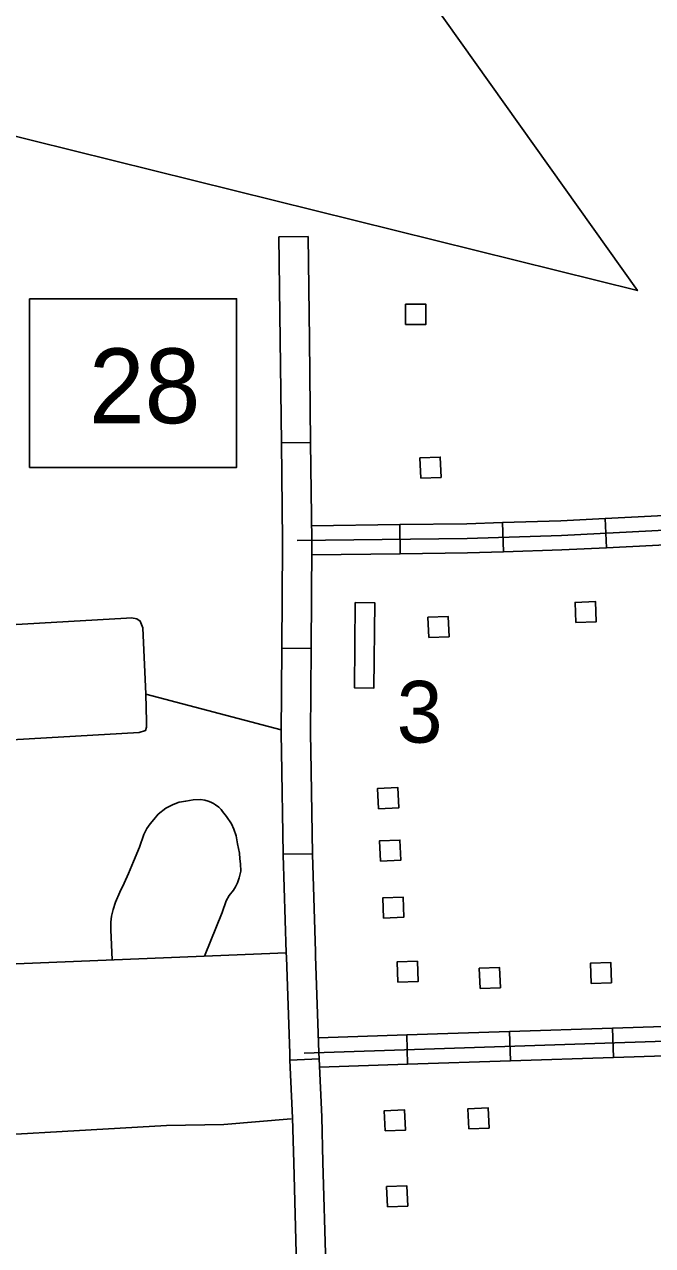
# Model space of a CAD drawing. Extents: x 1671357 to 13005564, y 567358 to 14261451.
# Drawn here: x 12758301.586 to 12758302.662, y 14259942.041 to 14259944.134 of the extents above; entities that cross this region are included whole.
import ezdxf

# ---------------------------------------------------------------- set-up
doc = ezdxf.new("R2010")
doc.units = 0
for name, color, linetype in [('31', 7, 'Continuous'), ('32', 7, 'Continuous'), ('56', 7, 'Continuous'), ('Default', 7, 'Continuous')]:
    doc.layers.add(name, color=color, linetype=linetype)

msp = doc.modelspace()

# ---------------------------------------------------------------- linework, layer by layer
at = {"layer": '31'}
for p, q in [((12758302.0222, 14259943.7697), (12758302.0722, 14259943.7703)), ((12758302.0764, 14259943.4177), (12758302.0263, 14259943.4171)), ((12758302.0771, 14259943.0647), (12758302.027, 14259943.0651)), ((12758302.0295, 14259942.7119), (12758302.0795, 14259942.7128)), ((12758302.041, 14259942.3589), (12758302.091, 14259942.3611)), ((12758302.041, 14259942.3589), (12758302.041, 14259942.3589))]:
    msp.add_line(p, q, dxfattribs=at)
for points in [[(12758302.0242, 14259943.5934), (12758302.0222, 14259943.7697)], [(12758302.0722, 14259943.7703), (12758302.0743, 14259943.594)], [(12758302.0263, 14259943.4171), (12758302.0242, 14259943.5934)], [(12758302.0743, 14259943.594), (12758302.0764, 14259943.4177)], [(12758302.0263, 14259943.4171), (12758302.0283, 14259943.2493), (12758302.0282, 14259943.2413)], [(12758302.0764, 14259943.4177), (12758302.0783, 14259943.2495), (12758302.0783, 14259943.241)], [(12758302.0282, 14259943.2413), (12758302.027, 14259943.0651)], [(12758302.0783, 14259943.241), (12758302.0771, 14259943.0647)], [(12758301.4006, 14259943.0738), (12758301.4045, 14259943.0354), (12758301.4372, 14259943.0364), (12758301.4715, 14259943.0382), (12758301.4876, 14259943.0453), (12758301.507, 14259943.0599), (12758301.5378, 14259943.0907), (12758301.5467, 14259943.1004), (12758301.5625, 14259943.1048), (12758301.7611, 14259943.1166), (12758301.7694, 14259943.117), (12758301.7785, 14259943.115), (12758301.7847, 14259943.1113), (12758301.7892, 14259943.0997), (12758301.794, 14259942.9863), (12758302.0259, 14259942.9248)], [(12758302.027, 14259943.0651), (12758302.026, 14259942.9181), (12758302.0265, 14259942.8882)], [(12758302.0766, 14259942.889), (12758302.0761, 14259942.9183), (12758302.0771, 14259943.0647)], [(12758301.4057, 14259942.8987), (12758301.7828, 14259942.9205), (12758301.7937, 14259942.924), (12758301.7951, 14259942.9294), (12758301.7954, 14259942.9391), (12758301.794, 14259942.9863)], [(12758302.0265, 14259942.8882), (12758302.0295, 14259942.7119)], [(12758302.0795, 14259942.7128), (12758302.0766, 14259942.889)], [(12758302.0295, 14259942.712), (12758302.0295, 14259942.7109), (12758302.0346, 14259942.5429), (12758302.0349, 14259942.5353)], [(12758302.0795, 14259942.7128), (12758302.0795, 14259942.7121), (12758302.0847, 14259942.5445), (12758302.0849, 14259942.537)], [(12758301.277, 14259942.5122), (12758302.0346, 14259942.5427)], [(12758302.0349, 14259942.5353), (12758302.0405, 14259942.3704), (12758302.041, 14259942.3589)], [(12758302.0849, 14259942.537), (12758302.0905, 14259942.3723), (12758302.091, 14259942.3611)], [(12758302.0475, 14259942.1832), (12758302.0453, 14259942.2601), (12758302.041, 14259942.3589)], [(12758302.091, 14259942.3611), (12758302.0954, 14259942.2619), (12758302.0975, 14259942.1845)], [(12758302.0523, 14259942.0069), (12758302.0475, 14259942.1832)], [(12758302.0975, 14259942.1845), (12758302.1024, 14259942.0083)]]:
    msp.add_lwpolyline(points, dxfattribs=at)
at = {"layer": '32'}
for p, q in [((12758302.2299, 14259943.2266), (12758302.2292, 14259943.2767)), ((12758302.4066, 14259943.2301), (12758302.405, 14259943.2801)), ((12758302.5832, 14259943.2371), (12758302.5807, 14259943.2871)), ((12758302.5949, 14259942.3638), (12758302.5932, 14259942.4139)), ((12758302.2425, 14259942.3521), (12758302.2409, 14259942.4022)), ((12758302.4187, 14259942.358), (12758302.417, 14259942.408))]:
    msp.add_line(p, q, dxfattribs=at)
for points in [[(12758302.0533, 14259943.2494), (12758302.3447, 14259943.2531), (12758302.5058, 14259943.2583), (12758302.6607, 14259943.2659), (12758302.9729, 14259943.2826), (12758303.0558, 14259943.2892), (12758303.0977, 14259943.2849), (12758303.1575, 14259943.2848), (12758303.554, 14259943.3051)], [(12758302.5807, 14259943.2871), (12758302.6594, 14259943.291), (12758302.7566, 14259943.2961)], [(12758302.078, 14259943.2748), (12758302.2292, 14259943.2767)], [(12758302.2292, 14259943.2767), (12758302.3441, 14259943.2782), (12758302.405, 14259943.2801)], [(12758302.405, 14259943.2801), (12758302.5047, 14259943.2833), (12758302.5807, 14259943.2871)], [(12758302.5832, 14259943.2371), (12758302.662, 14259943.2409), (12758302.7593, 14259943.2461)], [(12758302.0786, 14259943.2247), (12758302.2299, 14259943.2266)], [(12758302.2299, 14259943.2266), (12758302.3452, 14259943.2281), (12758302.4066, 14259943.2301)], [(12758302.4066, 14259943.2301), (12758302.5068, 14259943.2333), (12758302.5832, 14259943.2371)], [(12758301.7363, 14259942.5307), (12758301.7341, 14259942.5826), (12758301.7342, 14259942.5954), (12758301.7354, 14259942.6058), (12758301.7383, 14259942.617), (12758301.7424, 14259942.6296), (12758301.7497, 14259942.6467), (12758301.7571, 14259942.6621), (12758301.7647, 14259942.6788), (12758301.7732, 14259942.6997), (12758301.7831, 14259942.7242), (12758301.7906, 14259942.7457), (12758301.796, 14259942.756), (12758301.8014, 14259942.764), (12758301.8078, 14259942.7716), (12758301.8151, 14259942.7803), (12758301.8283, 14259942.7911), (12758301.8412, 14259942.7972), (12758301.8515, 14259942.801), (12758301.8626, 14259942.803), (12758301.8753, 14259942.805), (12758301.8876, 14259942.8058), (12758301.895, 14259942.8045), (12758301.9011, 14259942.8028), (12758301.9055, 14259942.8013), (12758301.9099, 14259942.7988), (12758301.9137, 14259942.7966), (12758301.9193, 14259942.7924), (12758301.9232, 14259942.7883), (12758301.9254, 14259942.7849), (12758301.9321, 14259942.7764), (12758301.9407, 14259942.764), (12758301.9449, 14259942.7547), (12758301.9489, 14259942.7432), (12758301.9514, 14259942.7296)], [(12758301.9511, 14259942.7296), (12758301.9545, 14259942.7137), (12758301.9552, 14259942.7041), (12758301.9565, 14259942.6954), (12758301.9566, 14259942.6827), (12758301.9543, 14259942.6715), (12758301.9513, 14259942.6627), (12758301.9475, 14259942.6559), (12758301.9441, 14259942.6504), (12758301.937, 14259942.6411), (12758301.9317, 14259942.6319), (12758301.925, 14259942.6119), (12758301.8946, 14259942.537)], [(12758302.0655, 14259942.3713), (12758303.3875, 14259942.4151)], [(12758302.417, 14259942.408), (12758302.5932, 14259942.4139)], [(12758302.5932, 14259942.4139), (12758302.7694, 14259942.4197)], [(12758302.0897, 14259942.3972), (12758302.2409, 14259942.4022)], [(12758302.2409, 14259942.4022), (12758302.417, 14259942.408)], [(12758302.5949, 14259942.3638), (12758302.7711, 14259942.3696)], [(12758302.0916, 14259942.3472), (12758302.2425, 14259942.3521)], [(12758302.2425, 14259942.3521), (12758302.4187, 14259942.358)], [(12758302.4187, 14259942.358), (12758302.5949, 14259942.3638)], [(12758301.3925, 14259942.2218), (12758301.8298, 14259942.2469), (12758301.9275, 14259942.249), (12758302.043, 14259942.2587)]]:
    msp.add_lwpolyline(points, dxfattribs=at)
at = {"layer": '56'}
for points in [[(12758302.2391, 14259943.6197), (12758302.2391, 14259943.6544), (12758302.2739, 14259943.6544), (12758302.2739, 14259943.6197)], [(12758302.2651, 14259943.3562), (12758302.2636, 14259943.3909), (12758302.2984, 14259943.3924), (12758302.2999, 14259943.3576)], [(12758302.1528, 14259943.1431), (12758302.1862, 14259943.1428), (12758302.1848, 14259942.9967), (12758302.1514, 14259942.9971)], [(12758302.5308, 14259943.1088), (12758302.5293, 14259943.1435), (12758302.5641, 14259943.145), (12758302.5656, 14259943.1103)], [(12758302.2786, 14259943.0832), (12758302.2771, 14259943.1179), (12758302.3119, 14259943.1194), (12758302.3134, 14259943.0847)], [(12758302.1924, 14259942.7898), (12758302.1909, 14259942.8245), (12758302.2258, 14259942.826), (12758302.2273, 14259942.7913)], [(12758302.1958, 14259942.7002), (12758302.1944, 14259942.7349), (12758302.2292, 14259942.7363), (12758302.2306, 14259942.7015)], [(12758302.2012, 14259942.6025), (12758302.1999, 14259942.6372), (12758302.2347, 14259942.6386), (12758302.236, 14259942.6039)], [(12758302.2259, 14259942.4926), (12758302.2245, 14259942.5273), (12758302.2593, 14259942.5286), (12758302.2607, 14259942.4939)], [(12758302.3665, 14259942.4817), (12758302.3652, 14259942.5164), (12758302.4, 14259942.5177), (12758302.4014, 14259942.483)], [(12758302.5568, 14259942.4903), (12758302.5554, 14259942.525), (12758302.5902, 14259942.5264), (12758302.5916, 14259942.4917)], [(12758302.2038, 14259942.2377), (12758302.2024, 14259942.2724), (12758302.2373, 14259942.2738), (12758302.2386, 14259942.239)], [(12758302.3471, 14259942.2412), (12758302.3458, 14259942.2759), (12758302.3806, 14259942.2773), (12758302.382, 14259942.2426)], [(12758302.2078, 14259942.1076), (12758302.2064, 14259942.1424), (12758302.2413, 14259942.1437), (12758302.2426, 14259942.109)]]:
    msp.add_lwpolyline(points, close=True, dxfattribs=at)
at = {"layer": 'Default'}
msp.add_lwpolyline([(12758300.287, 14259944.2608), (12758302.6359, 14259943.6777), (12758302.1816, 14259944.3171)], dxfattribs=at)
msp.add_lwpolyline([(12758301.595, 14259943.6638), (12758301.9496, 14259943.6638), (12758301.9496, 14259943.3748), (12758301.595, 14259943.3748)], close=True, dxfattribs=at)

# ---------------------------------------------------------------- texts
at = {"layer": '56'}
msp.add_text('3', height=0.1058, dxfattribs=at).set_placement((12758302.2237, 14259942.9031))
at = {"layer": 'Default'}
msp.add_text('28', height=0.12825, dxfattribs=at).set_placement((12758301.6968, 14259943.4504))

doc.saveas('drawing.dxf')
